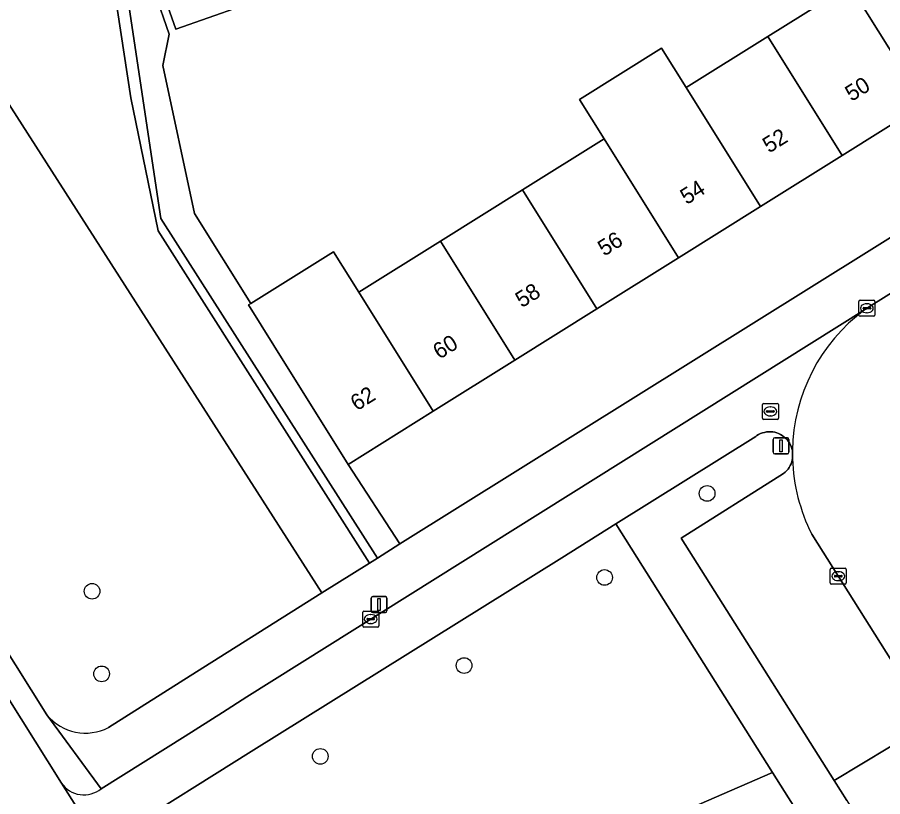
# Model space of a CAD drawing. Extents: x 160077 to 160948, y 386481 to 387498.
# Drawn here: x 160177.9 to 160232, y 387199.8 to 387248.5 of the extents above; entities that cross this region are included whole.
import ezdxf

# ---------------------------------------------------------------- set-up
doc = ezdxf.new("R2010")
doc.units = 0
for name, color, linetype in [('IMGEO_Boom', 7, 'Continuous'), ('IMGEO_Erf', 7, 'Continuous'), ('IMGEO_Fietspad_gesloten', 7, 'Continuous'), ('IMGEO_Fietspad_open', 7, 'Continuous'), ('IMGEO_Groenvoorziening', 7, 'Continuous'), ('IMGEO_Haag', 7, 'Continuous'), ('IMGEO_Kolk', 7, 'Continuous'), ('IMGEO_Lichtmast', 7, 'Continuous'), ('IMGEO_Pand', 7, 'Continuous'), ('IMGEO_Pand_nummerreeks', 7, 'Continuous'), ('IMGEO_Parkeervlak_open', 7, 'Continuous'), ('IMGEO_Rijbaan_lokaal_open', 7, 'Continuous'), ('IMGEO_Rioolput', 7, 'Continuous'), ('IMGEO_Voetpad_open', 7, 'Continuous')]:
    doc.layers.add(name, color=color, linetype=linetype)

msp = doc.modelspace()

# ---------------------------------------------------------------- linework, layer by layer
at = {"layer": 'IMGEO_Boom'}
for centre in [(160221.024, 387218.784), (160214.615, 387213.534), (160182.587, 387212.673), (160205.833, 387208.034), (160183.185, 387207.513), (160196.85, 387202.357)]:
    msp.add_circle(centre, 0.489, dxfattribs=at)
at = {"layer": 'IMGEO_Erf'}
msp.add_lwpolyline([(160253.275, 387247.762), (160250.114, 387252.824), (160245.599, 387250), (160244.804, 387249.503), (160239.691, 387246.305), (160234.579, 387243.107), (160229.466, 387239.91), (160224.355, 387236.713), (160219.242, 387233.515), (160214.129, 387230.317), (160209.017, 387227.119), (160203.904, 387223.922), (160198.595, 387220.601), (160201.816, 387215.631)], close=True, dxfattribs=at)
for points in [[(160186.511, 387250.087), (160187.412, 387247.484), (160187.016, 387245.526), (160188.979, 387236.286), (160192.502, 387230.654), (160197.672, 387233.887), (160199.255, 387231.356), (160204.367, 387234.554), (160209.48, 387237.751), (160214.592, 387240.949), (160213.055, 387243.407), (160218.168, 387246.605), (160219.705, 387244.147), (160224.817, 387247.344), (160229.064, 387250)], [(160191.864, 387249.21), (160187.813, 387247.797), (160186.96, 387250.243)]]:
    msp.add_lwpolyline(points, dxfattribs=at)
at = {"layer": 'IMGEO_Fietspad_gesloten'}
msp.add_lwpolyline([(160223.762, 387132.086), (160222.926, 387133.369), (160185.895, 387192.376), (160184.005, 387195.408), (160180.666, 387200.687), (160159.923, 387233.732), (160141.59, 387262.907), (160139.072, 387265.739)], dxfattribs=at)
at = {"layer": 'IMGEO_Fietspad_open'}
for points in [[(160230.858, 387230.252), (160192.259, 387206.087), (160190.744, 387205.097), (160188.403, 387203.609), (160183.16, 387200.334)], [(160211.947, 387214.771), (160215.32, 387216.878), (160224.07, 387222.353), (160224.134, 387222.398), (160224.245, 387222.465), (160224.362, 387222.522), (160224.482, 387222.567), (160224.607, 387222.602), (160224.734, 387222.626), (160224.863, 387222.638), (160224.992, 387222.639), (160225.121, 387222.628), (160225.248, 387222.606), (160225.373, 387222.572), (160225.495, 387222.527), (160225.611, 387222.472), (160225.723, 387222.406), (160225.828, 387222.331), (160225.926, 387222.247), (160226.016, 387222.154), (160226.098, 387222.053), (160226.17, 387221.946), (160226.232, 387221.833), (160226.284, 387221.714), (160226.325, 387221.592), (160226.355, 387221.466)], [(160184.423, 387197.569), (160192.529, 387202.664), (160211.947, 387214.771)], [(160180.666, 387200.687), (160184.005, 387195.408)]]:
    msp.add_lwpolyline(points, dxfattribs=at)
for centre, radius, start, end in [((160237.513, 387221.294), 11.159, 126.6099, 179.118), ((160182.079, 387201.681), 1.727, 215.1194, 308.7684)]:
    msp.add_arc(centre, radius, start, end, dxfattribs=at)
at = {"layer": 'IMGEO_Groenvoorziening'}
for points in [[(160200.429, 387214.746), (160186.881, 387235.961), (160184.772, 387250), (160180.628, 387277.584), (160156.25, 387273.768), (160156.25, 387272.976), (160158.866, 387273.206), (160162.399, 387273.873), (160179.971, 387276.547), (160185, 387243.499), (160186.713, 387235.199), (160199.92, 387214.428)], [(160199.92, 387214.428), (160186.713, 387235.199), (160185, 387243.499), (160179.971, 387276.547), (160162.399, 387273.873), (160158.866, 387273.206), (160156.25, 387272.976), (160156.25, 387273.768), (160155.14, 387273.594), (160155.915, 387269.341), (160160.624, 387269.243), (160172.96, 387250), (160196.955, 387212.573)]]:
    msp.add_lwpolyline(points, close=True, dxfattribs=at)
for points in [[(160139.615, 387268.878), (160142.864, 387263.696), (160161.126, 387234.638), (160179.769, 387204.942)], [(160183.618, 387204.16), (160189.118, 387207.631), (160196.955, 387212.573), (160172.96, 387250)], [(160235.799, 387137.046), (160230.812, 387134.941), (160208.795, 387187.088), (160213.806, 387189.204), (160211.661, 387194.284), (160216.461, 387196.334), (160216.109, 387197.157), (160218.173, 387198.038), (160218.06, 387198.303), (160218.439, 387198.463), (160225.112, 387201.343), (160215.32, 387216.878), (160211.947, 387214.771), (160192.529, 387202.664), (160184.423, 387197.569), (160187.198, 387193.134), (160224.187, 387134.187), (160225.336, 387132.427)]]:
    msp.add_lwpolyline(points, dxfattribs=at)
msp.add_arc((160182.179, 387206.939), 3.129, 219.6444, 297.3867, dxfattribs=at)
at = {"layer": 'IMGEO_Haag'}
msp.add_lwpolyline([(160200.429, 387214.746), (160186.881, 387235.961), (160184.772, 387250), (160180.628, 387277.584), (160156.25, 387273.768), (160156.25, 387272.976), (160158.866, 387273.206), (160162.399, 387273.873), (160179.971, 387276.547), (160185, 387243.499), (160186.713, 387235.199), (160199.92, 387214.428)], close=True, dxfattribs=at)
at = {"layer": 'IMGEO_Kolk'}
for p, q in [((160230.507, 387229.932), (160230.507, 387230.784)), ((160230.582, 387230.858), (160231.434, 387230.858)), ((160230.995, 387230.638), (160231.02, 387230.638)), ((160231.508, 387230.784), (160231.508, 387229.932)), ((160230.766, 387230.352), (160230.766, 387230.364)), ((160231.204, 387230.315), (160230.806, 387230.315)), ((160230.809, 387230.401), (160231.207, 387230.401)), ((160231.018, 387230.078), (160230.993, 387230.078)), ((160231.25, 387230.364), (160231.25, 387230.352)), ((160231.434, 387229.858), (160230.582, 387229.858)), ((160228.72, 387213.19), (160228.72, 387214.042)), ((160228.795, 387214.116), (160229.647, 387214.116)), ((160229.208, 387213.896), (160229.233, 387213.896)), ((160229.721, 387214.042), (160229.721, 387213.19)), ((160228.979, 387213.61), (160228.979, 387213.622)), ((160229.417, 387213.573), (160229.019, 387213.573)), ((160229.022, 387213.659), (160229.42, 387213.659)), ((160229.231, 387213.336), (160229.206, 387213.336)), ((160229.463, 387213.622), (160229.463, 387213.61)), ((160229.647, 387213.116), (160228.795, 387213.116)), ((160199.498, 387210.508), (160199.498, 387211.36)), ((160199.573, 387211.434), (160200.425, 387211.434)), ((160199.986, 387211.214), (160200.011, 387211.214)), ((160200.499, 387211.36), (160200.499, 387210.508)), ((160199.757, 387210.928), (160199.757, 387210.94)), ((160200.195, 387210.891), (160199.797, 387210.891)), ((160199.8, 387210.977), (160200.198, 387210.977)), ((160200.009, 387210.654), (160199.984, 387210.654)), ((160200.241, 387210.94), (160200.241, 387210.928)), ((160200.425, 387210.434), (160199.573, 387210.434))]:
    msp.add_line(p, q, dxfattribs=at)
for points in [[(160230.507, 387229.932), (160230.507, 387230.784)], [(160230.582, 387230.858), (160231.434, 387230.858)], [(160231.508, 387230.784), (160231.508, 387229.932)], [(160231.434, 387229.858), (160230.582, 387229.858)], [(160228.72, 387213.19), (160228.72, 387214.042)], [(160228.795, 387214.116), (160229.647, 387214.116)], [(160229.721, 387214.042), (160229.721, 387213.19)], [(160229.647, 387213.116), (160228.795, 387213.116)], [(160199.498, 387210.508), (160199.498, 387211.36)], [(160199.573, 387211.434), (160200.425, 387211.434)], [(160200.499, 387211.36), (160200.499, 387210.508)], [(160200.425, 387210.434), (160199.573, 387210.434)]]:
    msp.add_lwpolyline(points, dxfattribs=at)
for centre, radius, start, end in [((160230.584, 387230.782), 0.0765, 91.552, 178.448), ((160230.584, 387230.782), 0.0765, 91.552, 178.448), ((160231.432, 387230.782), 0.0765, 1.552, 88.448), ((160231.432, 387230.782), 0.0765, 1.552, 88.448), ((160230.806, 387230.361), 0.0403, 85.8775, 175.7526), ((160230.803, 387230.351), 0.0366, 178.938, 274.7102), ((160231.207, 387230.358), 0.043, 264.8664, 352.4533), ((160231.211, 387230.363), 0.0386, 1.7309, 96.639), ((160230.584, 387229.934), 0.0765, 181.552, 268.448), ((160230.584, 387229.934), 0.0765, 181.552, 268.448), ((160231.432, 387229.934), 0.0765, 271.552, 358.448), ((160231.432, 387229.934), 0.0765, 271.552, 358.448), ((160228.797, 387214.04), 0.0765, 91.552, 178.448), ((160228.797, 387214.04), 0.0765, 91.552, 178.448), ((160229.645, 387214.04), 0.0765, 1.552, 88.448), ((160229.645, 387214.04), 0.0765, 1.552, 88.448), ((160229.019, 387213.619), 0.0403, 85.8775, 175.7526), ((160229.016, 387213.609), 0.0366, 178.938, 274.7102), ((160229.42, 387213.616), 0.043, 264.8664, 352.4533), ((160229.424, 387213.621), 0.0386, 1.7309, 96.639), ((160228.797, 387213.192), 0.0765, 181.552, 268.448), ((160228.797, 387213.192), 0.0765, 181.552, 268.448), ((160229.645, 387213.192), 0.0765, 271.552, 358.448), ((160229.645, 387213.192), 0.0765, 271.552, 358.448), ((160199.575, 387211.358), 0.0765, 91.552, 178.448), ((160199.575, 387211.358), 0.0765, 91.552, 178.448), ((160200.423, 387211.358), 0.0765, 1.552, 88.448), ((160200.423, 387211.358), 0.0765, 1.552, 88.448), ((160199.575, 387210.51), 0.0765, 181.552, 268.448), ((160199.575, 387210.51), 0.0765, 181.552, 268.448), ((160199.797, 387210.937), 0.0403, 85.8775, 175.7526), ((160199.794, 387210.927), 0.0366, 178.938, 274.7102), ((160200.198, 387210.934), 0.043, 264.8664, 352.4533), ((160200.202, 387210.939), 0.0386, 1.7309, 96.639), ((160200.423, 387210.51), 0.0765, 271.552, 358.448), ((160200.423, 387210.51), 0.0765, 271.552, 358.448)]:
    msp.add_arc(centre, radius, start, end, dxfattribs=at)
for centre, major_axis, ratio, start_param, end_param in [((160230.994, 387230.358), (-0.387, 0.002), 0.722429, 4.712389, 7.853982), ((160231.019, 387230.358), (-0.39, 0.002), 0.717154, 1.570796, 4.712389), ((160229.207, 387213.616), (-0.387, 0.002), 0.722429, 4.712389, 7.853982), ((160229.232, 387213.616), (-0.39, 0.002), 0.717154, 1.570796, 4.712389), ((160199.985, 387210.934), (-0.387, 0.002), 0.722429, 4.712389, 7.853982), ((160200.01, 387210.934), (-0.39, 0.002), 0.717154, 1.570796, 4.712389)]:
    msp.add_ellipse(centre, major_axis=major_axis, ratio=ratio, start_param=start_param, end_param=end_param, dxfattribs=at)
at = {"layer": 'IMGEO_Lichtmast'}
for p, q in [((160225.148, 387221.359), (160225.148, 387222.159)), ((160225.148, 387222.159), (160225.148, 387221.359)), ((160225.248, 387222.259), (160226.038, 387222.259)), ((160226.038, 387222.259), (160225.248, 387222.259)), ((160226.138, 387222.159), (160226.138, 387221.359)), ((160226.138, 387221.359), (160226.138, 387222.159)), ((160226.038, 387221.259), (160225.248, 387221.259)), ((160225.248, 387221.259), (160226.038, 387221.259)), ((160200.028, 387211.441), (160200.028, 387212.241)), ((160200.028, 387212.241), (160200.028, 387211.441)), ((160200.128, 387212.341), (160200.918, 387212.341)), ((160200.918, 387212.341), (160200.128, 387212.341)), ((160201.018, 387212.241), (160201.018, 387211.441)), ((160201.018, 387211.441), (160201.018, 387212.241)), ((160200.918, 387211.341), (160200.128, 387211.341)), ((160200.128, 387211.341), (160200.918, 387211.341))]:
    msp.add_line(p, q, dxfattribs=at)
for points in [[(160225.568, 387222.134), (160225.718, 387222.134), (160225.718, 387221.384), (160225.568, 387221.384), (160225.568, 387222.134)], [(160200.448, 387212.216), (160200.598, 387212.216), (160200.598, 387211.466), (160200.448, 387211.466), (160200.448, 387212.216)]]:
    msp.add_lwpolyline(points, dxfattribs=at)
for centre, start, end in [((160225.248, 387222.159), 90, 180), ((160225.248, 387222.159), 90, 180), ((160226.038, 387222.159), 0, 90), ((160226.038, 387222.159), 360, 90), ((160225.248, 387221.359), 180, 270), ((160225.248, 387221.359), 180, 270), ((160226.038, 387221.359), 270, 0), ((160226.038, 387221.359), 270, 0), ((160200.128, 387212.241), 90, 180), ((160200.128, 387212.241), 90, 180), ((160200.918, 387212.241), 0, 90), ((160200.918, 387212.241), 360, 90), ((160200.128, 387211.441), 180, 270), ((160200.128, 387211.441), 180, 270), ((160200.918, 387211.441), 270, 0), ((160200.918, 387211.441), 270, 0)]:
    msp.add_arc(centre, 0.1, start, end, dxfattribs=at)
at = {"layer": 'IMGEO_Pand'}
for points in [[(160235.042, 387253.739), (160229.929, 387250.541), (160230.268, 387250), (160234.579, 387243.107), (160239.691, 387246.305), (160237.38, 387250)], [(160187.813, 387247.797), (160191.864, 387249.21), (160191.011, 387251.656), (160186.96, 387250.243)], [(160230.268, 387250), (160229.929, 387250.541), (160229.064, 387250), (160224.817, 387247.344), (160229.466, 387239.91), (160234.579, 387243.107)], [(160224.817, 387247.344), (160219.705, 387244.147), (160224.355, 387236.713), (160229.466, 387239.91)], [(160219.705, 387244.147), (160218.168, 387246.605), (160213.055, 387243.407), (160214.592, 387240.949), (160219.242, 387233.515), (160224.355, 387236.713)], [(160214.129, 387230.317), (160219.242, 387233.515), (160214.592, 387240.949), (160209.48, 387237.751)], [(160209.017, 387227.119), (160214.129, 387230.317), (160209.48, 387237.751), (160204.367, 387234.554)], [(160203.904, 387223.922), (160209.017, 387227.119), (160204.367, 387234.554), (160199.255, 387231.356)], [(160199.255, 387231.356), (160197.672, 387233.887), (160192.502, 387230.654), (160192.362, 387230.566), (160193.945, 387228.035), (160198.595, 387220.601), (160203.904, 387223.922)]]:
    msp.add_lwpolyline(points, close=True, dxfattribs=at)
at = {"layer": 'IMGEO_Parkeervlak_open'}
for points in [[(160226.36, 387220.948), (160226.349, 387220.891), (160226.316, 387220.766), (160226.273, 387220.645), (160226.218, 387220.528), (160226.154, 387220.417), (160226.08, 387220.311), (160225.996, 387220.213), (160225.904, 387220.123), (160225.805, 387220.041), (160219.401, 387215.993), (160228.959, 387200.845), (160234.151, 387203.974)], [(160250.335, 387180.106), (160227.566, 387216.245)]]:
    msp.add_lwpolyline(points, dxfattribs=at)
msp.add_arc((160237.468, 387221.29), 11.114, 181.7657, 206.9994, dxfattribs=at)
at = {"layer": 'IMGEO_Rijbaan_lokaal_open'}
for points in [[(160234.972, 387224.586), (160246.012, 387231.489), (160242.323, 387237.407), (160231.101, 387230.415), (160230.944, 387230.31), (160230.858, 387230.252)], [(160226.355, 387221.466), (160226.36, 387220.948)], [(160227.566, 387216.245), (160250.335, 387180.106), (160272.691, 387144.583), (160281.95, 387150.406), (160278.216, 387156.343)]]:
    msp.add_lwpolyline(points, dxfattribs=at)
for centre, radius, start, end in [((160237.513, 387221.294), 11.159, 126.6099, 179.118), ((160237.468, 387221.29), 11.114, 181.7657, 206.9994)]:
    msp.add_arc(centre, radius, start, end, dxfattribs=at)
at = {"layer": 'IMGEO_Rioolput'}
for p, q in [((160224.477, 387223.485), (160224.477, 387224.337)), ((160224.552, 387224.411), (160225.404, 387224.411)), ((160224.965, 387224.191), (160224.99, 387224.191)), ((160225.478, 387224.337), (160225.478, 387223.485)), ((160224.736, 387223.905), (160224.736, 387223.917)), ((160225.174, 387223.868), (160224.776, 387223.868)), ((160224.779, 387223.954), (160225.177, 387223.954)), ((160224.988, 387223.631), (160224.963, 387223.631)), ((160225.22, 387223.917), (160225.22, 387223.905)), ((160225.404, 387223.411), (160224.552, 387223.411))]:
    msp.add_line(p, q, dxfattribs=at)
for points in [[(160224.477, 387223.485), (160224.477, 387224.337)], [(160224.552, 387224.411), (160225.404, 387224.411)], [(160225.478, 387224.337), (160225.478, 387223.485)], [(160225.404, 387223.411), (160224.552, 387223.411)]]:
    msp.add_lwpolyline(points, dxfattribs=at)
for centre, radius, start, end in [((160224.554, 387224.335), 0.0765, 91.552, 178.448), ((160224.554, 387224.335), 0.0765, 91.552, 178.448), ((160225.402, 387224.335), 0.0765, 1.552, 88.448), ((160225.402, 387224.335), 0.0765, 1.552, 88.448), ((160224.554, 387223.487), 0.0765, 181.552, 268.448), ((160224.554, 387223.487), 0.0765, 181.552, 268.448), ((160224.776, 387223.914), 0.0403, 85.8775, 175.7526), ((160224.773, 387223.904), 0.0366, 178.938, 274.7102), ((160225.177, 387223.911), 0.043, 264.8664, 352.4533), ((160225.181, 387223.916), 0.0386, 1.7309, 96.639), ((160225.402, 387223.487), 0.0765, 271.552, 358.448), ((160225.402, 387223.487), 0.0765, 271.552, 358.448)]:
    msp.add_arc(centre, radius, start, end, dxfattribs=at)
for centre, major_axis, ratio, start_param, end_param in [((160224.964, 387223.911), (-0.387, 0.002), 0.722429, 4.712389, 7.853982), ((160224.989, 387223.911), (-0.39, 0.002), 0.717154, 1.570796, 4.712389)]:
    msp.add_ellipse(centre, major_axis=major_axis, ratio=ratio, start_param=start_param, end_param=end_param, dxfattribs=at)
at = {"layer": 'IMGEO_Voetpad_open'}
for points in [[(160139.072, 387265.739), (160141.59, 387262.907), (160159.923, 387233.732), (160180.666, 387200.687)], [(160183.16, 387200.334), (160179.769, 387204.942), (160161.126, 387234.638), (160142.864, 387263.696)], [(160230.858, 387230.252), (160230.944, 387230.31), (160231.101, 387230.415), (160242.323, 387237.407), (160244.666, 387238.867), (160259.479, 387248.097), (160262.537, 387250), (160273.747, 387256.976), (160274.213, 387257.296), (160274.649, 387257.656), (160273.704, 387262.548)], [(160272.398, 387259.702), (160256.86, 387250), (160254.584, 387248.579), (160253.275, 387247.762), (160201.816, 387215.631), (160200.429, 387214.746), (160199.92, 387214.428), (160196.955, 387212.573), (160189.118, 387207.631), (160183.618, 387204.16)], [(160184.772, 387250), (160186.881, 387235.961), (160200.429, 387214.746), (160201.816, 387215.631), (160198.595, 387220.601), (160193.945, 387228.035), (160192.362, 387230.566), (160192.502, 387230.654), (160188.979, 387236.286), (160187.016, 387245.526), (160187.412, 387247.484), (160186.511, 387250.087)], [(160179.769, 387204.942), (160183.16, 387200.334), (160188.403, 387203.609), (160190.744, 387205.097), (160192.259, 387206.087), (160230.858, 387230.252)], [(160229.747, 387199.595), (160228.959, 387200.845), (160219.401, 387215.993), (160225.805, 387220.041), (160225.904, 387220.123), (160225.996, 387220.213), (160226.08, 387220.311), (160226.154, 387220.417), (160226.218, 387220.528), (160226.273, 387220.645), (160226.316, 387220.766), (160226.349, 387220.891), (160226.36, 387220.948), (160226.355, 387221.466), (160226.325, 387221.592), (160226.284, 387221.714), (160226.232, 387221.833), (160226.17, 387221.946), (160226.098, 387222.053), (160226.016, 387222.154), (160225.926, 387222.247), (160225.828, 387222.331), (160225.723, 387222.406), (160225.611, 387222.472), (160225.495, 387222.527), (160225.373, 387222.572), (160225.248, 387222.606), (160225.121, 387222.628), (160224.992, 387222.639), (160224.863, 387222.638), (160224.734, 387222.626), (160224.607, 387222.602), (160224.482, 387222.567), (160224.362, 387222.522), (160224.245, 387222.465), (160224.134, 387222.398), (160224.07, 387222.353), (160215.32, 387216.878), (160225.112, 387201.343), (160227.248, 387197.953)], [(160234.151, 387203.974), (160228.959, 387200.845), (160229.747, 387199.595), (160231.696, 387196.505), (160236.841, 387199.663)]]:
    msp.add_lwpolyline(points, dxfattribs=at)
msp.add_lwpolyline([(160227.248, 387197.953), (160225.112, 387201.343), (160218.439, 387198.463), (160220.057, 387194.673), (160219.791, 387194.56), (160220.847, 387192.086), (160221.11, 387192.199), (160221.39, 387191.545), (160221.144, 387191.439), (160221.92, 387189.603), (160224.298, 387190.633), (160223.332, 387192.863), (160228.93, 387195.285)], close=True, dxfattribs=at)
for centre, radius, start, end in [((160182.179, 387206.939), 3.129, 219.6444, 297.3867), ((160182.079, 387201.681), 1.727, 215.1194, 308.7684)]:
    msp.add_arc(centre, radius, start, end, dxfattribs=at)

# ---------------------------------------------------------------- texts
at = {"layer": 'IMGEO_Pand_nummerreeks'}
for s, rotation, p in [('50', 32.0243, (160230.049, 387243.246)), ('52', 32.0243, (160224.892, 387240.02)), ('54', 32.0226, (160219.742, 387236.8)), ('56', 32.0243, (160214.59, 387233.578)), ('58', 32.0243, (160209.441, 387230.356)), ('60', 32.0243, (160204.289, 387227.134)), ('62', 32.0226, (160199.132, 387223.909))]:
    msp.add_text(s, height=1, rotation=rotation, dxfattribs=at).set_placement(p)

doc.saveas('drawing.dxf')
